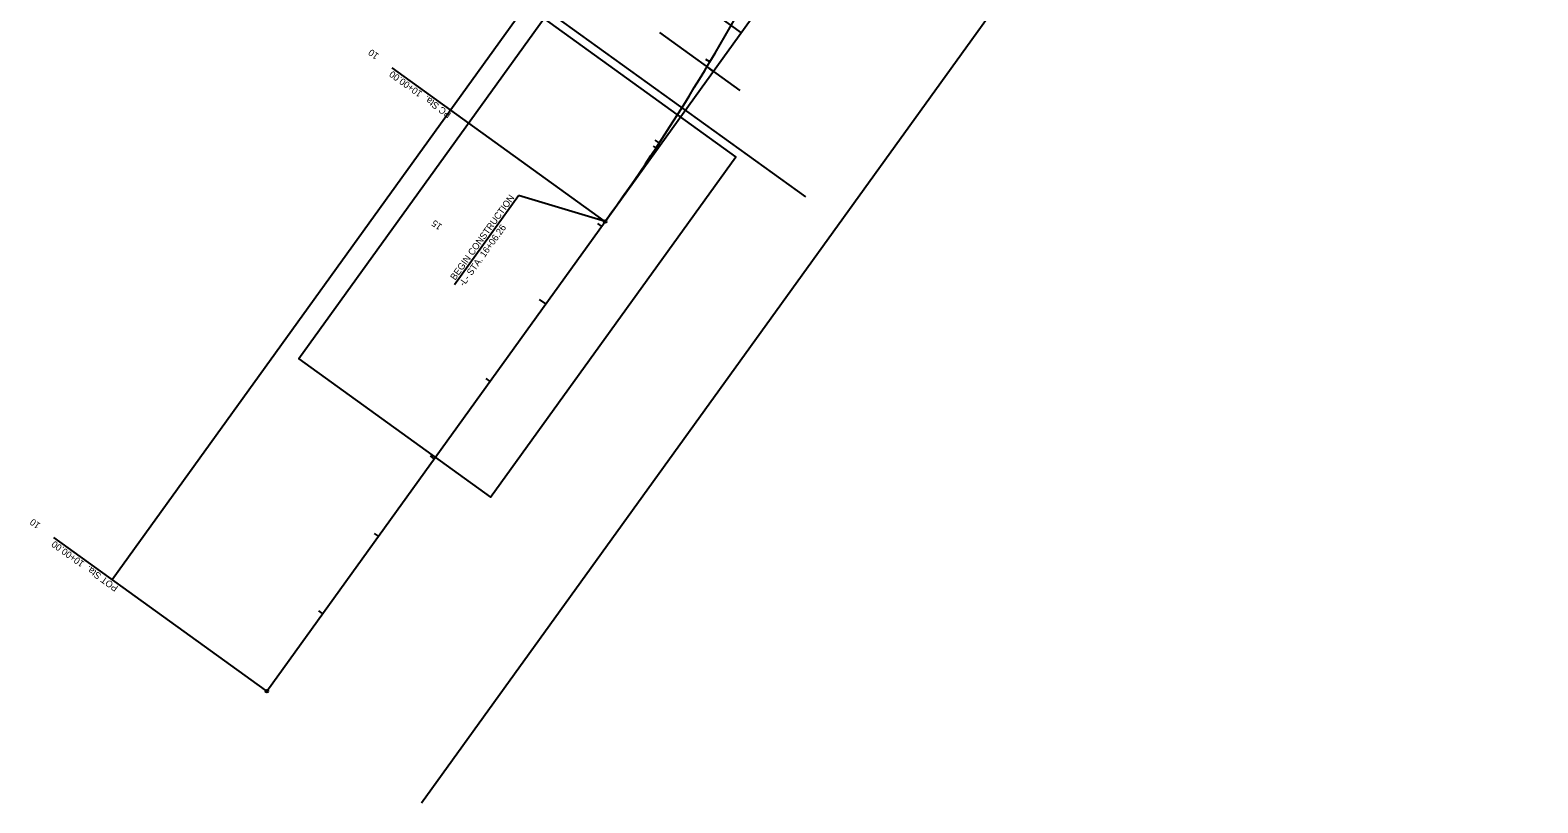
# Model space of a CAD drawing. Extents: x 2189281 to 2191267, y 386656 to 389012.
# Drawn here: x 2189281 to 2190861, y 386656 to 387465 of the extents above; entities that cross this region are included whole.
import ezdxf

# ---------------------------------------------------------------- set-up
doc = ezdxf.new("R2010")
doc.units = 0
for name, color, linetype in [('Prop DSN Text', 7, 'Continuous'), ('Prop Horizontal Alignment', 7, 'Continuous'), ('Prop Horizontal Alignment Station Label', 7, 'Continuous'), ('Prop Horizontal Alignment Tick Label', 7, 'Continuous'), ('Prop Horizontal Alignment Tick Large', 7, 'Continuous'), ('Prop Horizontal Alignment Tick Small', 7, 'Continuous'), ('Scratch_Level_3', 7, 'Continuous'), ('Scratch_Level_5', 7, 'Continuous')]:
    doc.layers.add(name, color=color, linetype=linetype)

msp = doc.modelspace()

# ---------------------------------------------------------------- linework, layer by layer
at = {"layer": 'Prop DSN Text'}
for p in [(2189726, 387198.8), (2189884, 387264.8)]:
    msp.add_line(p, (2189793.1, 387292), dxfattribs=at)
at = {"layer": 'Prop Horizontal Alignment'}
msp.add_line((2189529.4, 386773.1), (2190699.2, 388395.3), dxfattribs=at)
msp.add_arc((2188018.5, 388610.2), 2300, 324.2018, 332.5959, dxfattribs=at)
at = {"layer": 'Prop Horizontal Alignment Station Label'}
for p, q in [((2189882.8, 387265.7), (2189660.9, 387425.7)), ((2189528.2, 386774), (2189306.3, 386934))]:
    msp.add_line(p, q, dxfattribs=at)
for centre in [(2189884, 387264.8), (2189529.4, 386773.1)]:
    msp.add_circle(centre, 1.5, dxfattribs=at)
at = {"layer": 'Prop Horizontal Alignment Tick Large'}
for p, q in [((2189884, 387264.8), (2189877.5, 387269.5)), ((2189821.8, 387178.6), (2189815.3, 387183.3)), ((2189529.4, 386773.1), (2189522.9, 386777.8))]:
    msp.add_line(p, q, dxfattribs=at)
at = {"layer": 'Prop Horizontal Alignment Tick Small'}
for p, q in [((2189993.8, 387431.9), (2189989.5, 387434.5)), ((2189997.3, 387422), (2189993.3, 387424.9)), ((2189940.7, 387347.2), (2189936.5, 387349.9)), ((2189938.8, 387340.9), (2189934.8, 387343.8)), ((2189880.3, 387259.8), (2189876.3, 387262.7)), ((2189763.3, 387097.5), (2189759.3, 387100.5)), ((2189704.9, 387016.4), (2189700.8, 387019.4)), ((2189646.4, 386935.3), (2189642.3, 386938.2)), ((2189587.9, 386854.2), (2189583.8, 386857.1))]:
    msp.add_line(p, q, dxfattribs=at)
at = {"layer": 'Scratch_Level_3'}
msp.add_lwpolyline([(2189820.2, 387477.5), (2189563.1, 387121.1), (2189763.8, 386976.3), (2190020.9, 387332.7)], close=True, dxfattribs=at)
at = {"layer": 'Scratch_Level_5'}
for p, q in [((2189367.2, 386890.1), (2190537, 388512.3)), ((2189691.6, 386656.1), (2190861.5, 388278.3)), ((2189917.9, 387540.9), (2190026.6, 387462.5)), ((2189805.9, 387498.4), (2190093.9, 387290.6)), ((2189941, 387462.6), (2190025, 387402))]:
    msp.add_line(p, q, dxfattribs=at)

# ---------------------------------------------------------------- texts
at = {"layer": 'Prop DSN Text'}
for s, p in [('BEGIN CONSTRUCTION', (2189726.7, 387202.8)), ('-L- STA. 16+06.26', (2189735.8, 387196.3))]:
    msp.add_text(s, height=7, rotation=54.2018, dxfattribs=at).set_placement(p)
at = {"layer": 'Prop Horizontal Alignment Station Label'}
for s, p in [('PC Sta.  10+00.00', (2189723.3, 387378.2)), ('POT Sta.  10+00.00', (2189374.3, 386882.4))]:
    msp.add_text(s, height=7, rotation=144.2018, dxfattribs=at).set_placement(p)
at = {"layer": 'Prop Horizontal Alignment Tick Label'}
for s, p in [('10', (2189647.5, 387439.7)), ('15', (2189713.8, 387260.9)), ('10', (2189292.8, 386948))]:
    msp.add_text(s, height=7, rotation=144.2018, dxfattribs=at).set_placement(p)

doc.saveas('drawing.dxf')
